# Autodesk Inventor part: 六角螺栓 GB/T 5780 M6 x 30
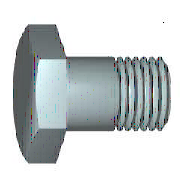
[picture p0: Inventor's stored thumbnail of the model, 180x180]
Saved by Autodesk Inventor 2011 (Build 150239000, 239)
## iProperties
Created: 2010-02
Part Number: 六角螺栓 GB/T 5780 M6 x 30
Material: 低炭钢
Description: 六角头螺栓 - 产品等级 C
Document SubType Name: Modeling
Standard: GB/T 5780-2000
Designer: Administrator
Standard Revision: 2000
Standards Organization: GB
Language: zh-CN
Size Designation: M6x30
Categories: <MemberInstance><Categories><Category DisplayName="紧固件" InternalName="e4da775c-781d-43d5-af7c-5136215cf5a6" Mnemonic="FSTN"><Category DisplayName="螺栓" InternalN
Density: 1 g/cm^3
IsCustomPart: 1
Author: Administrator
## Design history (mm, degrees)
fillet "Fillet2" dims "d71" = 0.25 (= RR)
workplane "Work Plane1"
sketch "Sketch1"
  geometry: L1 (0, 3)-(30, 3); L2 (30, 3)-(30, 0); L3 (30, 0)-(0, 0); L4 (-6, 0)-(36, 0) reference; L5 (0, -0.6)-(0, 3.6) reference; L6 (0, 3)-(0, 0)
  constraints: 8 end point, 3 point on line, 1 collinear
  dimensions: "d2" = 6 diameter of L1 L3 (= GD); "d59" = 30 distance between parallel lines of L2 L5 (= NLG)
revolve "Body" sketch "Sketch1" stored, may be unused: angle "d12" = 90 deg
sketch "Sketch2"
  geometry: L1 (0, 5.774)-(5, 2.887); L2 (5, 2.887)-(5, -2.887); L3 (5, -2.887)-(0, -5.774); L4 (0, -5.774)-(-5, -2.887); L5 (-5, -2.887)-(-5, 2.887); L6 (-5, 2.887)-(0, 5.774); L7 (-7, 0)-(7, 0) reference; L8 (0, 8.083)-(0, -8.083) reference; 2 further points
  constraints: 12 end point, 2 midpoint, 1 coincident, 1 vertical, 11 other
  dimensions: "d11" = 10 distance between parallel lines of L5 L2 (= SW)
extrude "Head" join sketch "Sketch2" distance "d3" = 4 (= KOH); taper "d4" = 0 deg
sketch "Sketch4"
  geometry: L1 (-3.423, 6)-(-4, 5); L2 (-1.1, 0)-(-0.234, 0); L3 (-4.753, 0)-(0.519, 0) reference; L4 (-4, 6)-(-3.423, 6); L5 (-4, 5)-(-4, 6); L6 (0, 7.2)-(0, -1.2) reference
  constraints: 8 end point, 1 parallel, 1 perpendicular, 1 point on line
  dimensions: "d65" = 10 diameter of L1.end L2 (= SW); "d67" = 30 deg angle of L1 L5 (= ANG1); "d68" = 12 diameter of L4 L2 (= 1.2 x SW); "d69" = 4 distance between parallel lines of L5 L6 (= KOH)
revolve "Chamfer1" stored, may be unused: angle "d21" = 90 deg
chamfer "Chamfer2" distance "d6" = 0.61345 (= -0.5 x SPD + 0.5 x GD); stored, may be unused: second distance "d7" = 0.61355 (computed from GUL), angle "d55" = 45 deg
feature "Thread" dims "d15" = 18 (= GEL), "d16" = 0
body "Solid1"
other parameters: "NLG" = 30 [user parameter; used in 1 equation term], "GD" = 6 (= NND) [user parameter; used in 2 equation terms], "BDM" = 6 (= NND) [user parameter], "KOH" = 4 [user parameter; used in 2 equation terms], "GEL" = 18 [user parameter; used in 1 equation term], "SW" = 10 [user parameter; used in 6 equation terms], "SPD" = 4.7731 (= NND - 1.2269 x PTC) [user parameter; used in 1 equation term], "SD2" = 6 (= NND) [user parameter], "SD" = 0 [user parameter], "ANG1" = 30 deg [user parameter; used in 1 equation term], "GAL" = 0.61345 (= 0.61345 x PTC) [user parameter], "GUL" = 0.61345 (= 0.61345 x PTC) [user parameter; used in 1 equation term], "d8" = 0, "RR" = 0.25 [user parameter; used in 1 equation term], "d58" = 0, "RR1" = 0.1 [user parameter], "d73" = 0, "WFT" = 0 [user parameter], "GD1" = 4.7731 (= THREADDIA - 1.2269 x PTC) [user parameter], "THREADDIA" = 6 [user parameter; used in 1 equation term], "TOA" = 30 deg [user parameter], "FAWI" = 90 deg [user parameter], "PTC" = 1 [user parameter; used in 5 equation terms], "NND" = 6 [user parameter; used in 4 equation terms], "E0" = 11.55 (= 1.155 x SW) [user parameter]
